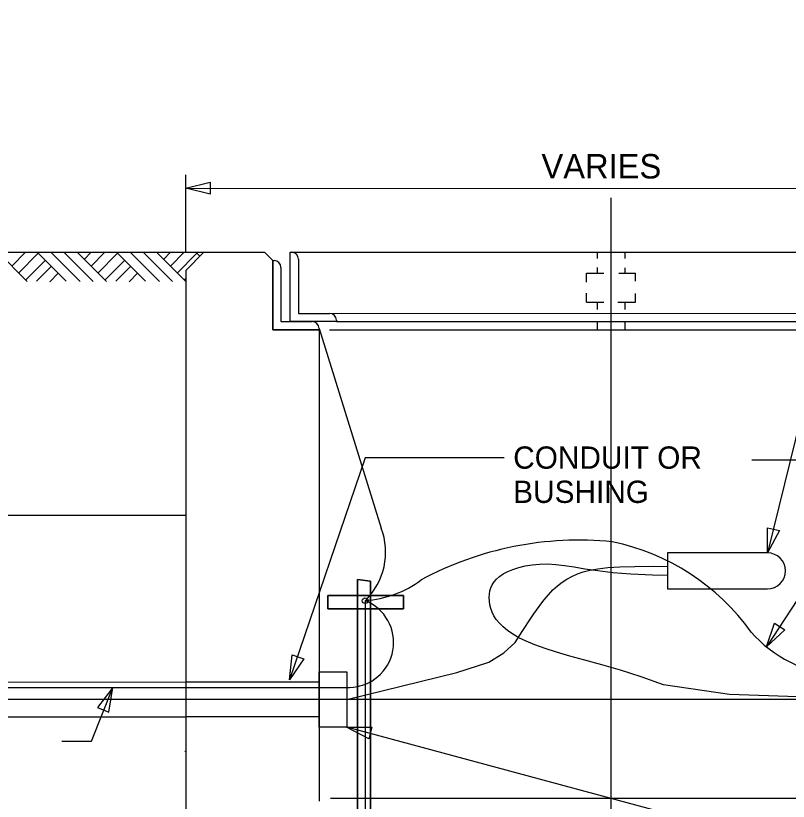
# Model space of a CAD drawing. Extents: x 1299104.8 to 1299141.6, y 239639.8 to 239661.8.
# Drawn here: x 1299124.467 to 1299128.261, y 239648.164 to 239652.024 of the extents above; entities that cross this region are included whole.
import ezdxf

# ---------------------------------------------------------------- set-up
doc = ezdxf.new("R2010")
doc.units = 0
doc.layers.add('DIM TXT', color=7, linetype='Continuous')

msp = doc.modelspace()

# ---------------------------------------------------------------- linework, layer by layer
at = {"layer": 'DIM TXT'}
for p, q in [((1299128.804, 239652.0235), (1299128.1595, 239649.3845)), ((1299125.3013, 239650.8613), (1299125.3013, 239651.2424)), ((1299125.3013, 239651.1756), (1299129.4791, 239651.1753)), ((1299127.3903, 239651.1285), (1299127.3903, 239650.0543)), ((1299123.9914, 239650.8613), (1299125.3906, 239650.8613)), ((1299124.5226, 239650.7182), (1299124.3784, 239650.8613)), ((1299124.5148, 239650.8613), (1299124.4475, 239650.7934)), ((1299124.5764, 239650.8563), (1299124.4803, 239650.7594)), ((1299124.7143, 239650.7194), (1299124.5714, 239650.8613)), ((1299124.7827, 239650.7182), (1299124.6385, 239650.8613)), ((1299124.8475, 239650.7182), (1299124.7033, 239650.8613)), ((1299124.9124, 239650.7182), (1299124.7682, 239650.8613)), ((1299124.8373, 239650.8613), (1299124.803, 239650.8267)), ((1299124.9047, 239650.8613), (1299124.8373, 239650.7934)), ((1299124.9663, 239650.8563), (1299124.8701, 239650.7594)), ((1299125.1041, 239650.7194), (1299124.9613, 239650.8613)), ((1299125.1725, 239650.7182), (1299125.0283, 239650.8613)), ((1299125.2374, 239650.7182), (1299125.0932, 239650.8613)), ((1299125.3023, 239650.7182), (1299125.1581, 239650.8613)), ((1299125.2271, 239650.8613), (1299125.1929, 239650.8267)), ((1299125.2945, 239650.8613), (1299125.2272, 239650.7934)), ((1299125.3561, 239650.8563), (1299125.26, 239650.7594)), ((1299125.3016, 239650.7723), (1299125.3906, 239650.8613)), ((1299125.3709, 239650.8416), (1299125.3511, 239650.8613)), ((1299125.3906, 239650.8613), (1299125.6891, 239650.8613)), ((1299125.6891, 239650.8613), (1299125.7292, 239650.8212)), ((1299125.8151, 239650.8618), (1299125.8212, 239650.8618)), ((1299125.8151, 239650.8618), (1299128.2296, 239650.8618)), ((1299127.3225, 239650.8618), (1299127.3225, 239650.8314)), ((1299127.4581, 239650.8618), (1299127.4581, 239650.83)), ((1299128.2296, 239650.8618), (1299128.9655, 239650.8618)), ((1299124.6114, 239650.8215), (1299124.516, 239650.7254)), ((1299125.0013, 239650.8215), (1299124.9058, 239650.7254)), ((1299125.7292, 239650.8212), (1299125.7353, 239650.8212)), ((1299125.7292, 239650.8212), (1299125.7292, 239650.4807)), ((1299124.6413, 239650.7919), (1299124.5688, 239650.7189)), ((1299125.0311, 239650.7919), (1299124.9586, 239650.7189)), ((1299125.3013, 239650.7719), (1299125.3013, 239648.4563)), ((1299127.3225, 239650.7865), (1299127.3225, 239650.7592)), ((1299127.4581, 239650.7851), (1299127.4581, 239650.7592)), ((1299124.6748, 239650.7586), (1299124.6334, 239650.7169)), ((1299125.0646, 239650.7586), (1299125.0233, 239650.7169)), ((1299125.3013, 239650.731), (1299125.2957, 239650.7254)), ((1299127.2693, 239650.7151), (1299127.2693, 239650.7592)), ((1299127.2693, 239650.7592), (1299127.3547, 239650.7592)), ((1299127.4289, 239650.7592), (1299127.5113, 239650.7592)), ((1299127.5113, 239650.7193), (1299127.5113, 239650.7592)), ((1299127.2693, 239650.6156), (1299127.2693, 239650.6604)), ((1299127.5113, 239650.6156), (1299127.5113, 239650.659)), ((1299127.2693, 239650.6156), (1299127.3547, 239650.6156)), ((1299127.3225, 239650.6156), (1299127.3225, 239650.5809)), ((1299127.4233, 239650.6156), (1299127.5113, 239650.6156)), ((1299127.4581, 239650.6156), (1299127.4581, 239650.5809)), ((1299126.008, 239650.5614), (1299128.7725, 239650.5615)), ((1299126.0421, 239650.5274), (1299126.0421, 239650.5213)), ((1299126.0421, 239650.5213), (1299128.7385, 239650.5213)), ((1299126.1215, 239650.5213), (1299126.5162, 239650.5213)), ((1299126.6845, 239650.5213), (1299126.798, 239650.5213)), ((1299126.7222, 239650.5213), (1299127.0215, 239650.5213)), ((1299127.3225, 239650.5213), (1299127.3225, 239650.4818)), ((1299127.4581, 239650.5213), (1299127.4581, 239650.4818)), ((1299125.7292, 239650.4807), (1299125.9562, 239650.4807)), ((1299125.9562, 239650.4867), (1299125.9562, 239650.4807)), ((1299125.9562, 239650.4867), (1299126.2613, 239649.5068)), ((1299125.9562, 239650.4807), (1299125.9562, 239650.1869)), ((1299126.008, 239650.4807), (1299126.2742, 239650.4807)), ((1299126.2742, 239650.4807), (1299128.4396, 239650.4807)), ((1299125.9562, 239650.1869), (1299125.9562, 239648.1643)), ((1299127.3903, 239650.0543), (1299127.3903, 239646.816)), ((1299124.0638, 239649.5699), (1299125.3013, 239649.5699)), ((1299126.1827, 239649.1498), (1299126.1827, 239646.4459)), ((1299126.9546, 239648.9982), (1299127.0021, 239649.0704)), ((1299126.9199, 239648.9447), (1299126.9546, 239648.9982)), ((1299126.8635, 239648.8937), (1299126.9199, 239648.9447)), ((1299126.791, 239648.8476), (1299126.8635, 239648.8937)), ((1299126.6326, 239648.7976), (1299126.791, 239648.8476)), ((1299126.0924, 239648.6647), (1299126.6326, 239648.7976)), ((1299123.0217, 239648.7524), (1299125.3022, 239648.7501)), ((1299123.0217, 239648.7234), (1299126.1065, 239648.7237)), ((1299125.9562, 239648.7498), (1299125.3013, 239648.7498)), ((1299132.1436, 239648.6647), (1299122.9138, 239648.6647)), ((1299123.0217, 239648.5795), (1299125.3013, 239648.5793)), ((1299125.9564, 239648.5793), (1299125.3013, 239648.5793)), ((1299125.9562, 239648.5285), (1299125.9562, 239648.5285)), ((1299125.3016, 239648.5034), (1299125.3016, 239647.5623)), ((1299125.3003, 239648.4088), (1299125.2972, 239648.4084)), ((1299126.0134, 239648.1789), (1299128.7717, 239648.1789))]:
    msp.add_line(p, q, dxfattribs=at)
for points in [[(1299129.9567, 239651.3812), (1299129.7633, 239651.3812), (1299128.1534, 239648.9236)], [(1299126.0421, 239650.5213), (1299125.8151, 239650.5213), (1299125.8151, 239650.8618)], [(1299125.9562, 239650.4807), (1299125.7292, 239650.4807), (1299125.7292, 239650.8212)], [(1299125.8552, 239650.8278), (1299125.8552, 239650.5614), (1299126.008, 239650.5614)], [(1299125.7693, 239650.7871), (1299125.7693, 239650.5208), (1299125.9222, 239650.5208)], [(1299126.8663, 239649.8521), (1299126.1832, 239649.8523), (1299125.8116, 239648.7617)], [(1299128.0822, 239649.8412), (1299128.3529, 239649.8412), (1299128.6881, 239648.8009)], [(1299128.1595, 239649.3845), (1299127.6671, 239649.3845), (1299127.6671, 239649.2082), (1299128.1595, 239649.2082)], [(1299128.6881, 239648.6647), (1299127.9731, 239648.6881), (1299127.6489, 239648.7358), (1299127.5381, 239648.7761), (1299127.4368, 239648.8086), (1299127.3448, 239648.8352), (1299127.262, 239648.8575), (1299127.1882, 239648.8775), (1299127.1231, 239648.8964), (1299127.0662, 239648.9148), (1299127.0169, 239648.9328), (1299126.9744, 239648.9504), (1299126.9381, 239648.9679), (1299126.9074, 239648.9854), (1299126.8815, 239649.0029), (1299126.8599, 239649.0207), (1299126.8419, 239649.0387), (1299126.8271, 239649.057), (1299126.8154, 239649.0754), (1299126.8065, 239649.0938), (1299126.8, 239649.1121), (1299126.7956, 239649.1301), (1299126.7933, 239649.1478), (1299126.7925, 239649.1651), (1299126.7933, 239649.1818), (1299126.7957, 239649.1979), (1299126.8, 239649.2134), (1299126.8066, 239649.2283), (1299126.8157, 239649.2425), (1299126.8277, 239649.2562), (1299126.8427, 239649.2691), (1299126.8611, 239649.2814), (1299126.8831, 239649.2929), (1299126.9086, 239649.3035), (1299126.9372, 239649.3127), (1299126.9687, 239649.3202), (1299127.0029, 239649.3259), (1299127.0395, 239649.3292), (1299127.0783, 239649.33), (1299127.119, 239649.3279), (1299127.1618, 239649.3228), (1299127.2088, 239649.3154), (1299127.2624, 239649.3066), (1299127.3253, 239649.2973), (1299127.3998, 239649.2885), (1299127.4885, 239649.2811), (1299127.5939, 239649.276), (1299127.6671, 239649.2748)], [(1299127.0021, 239649.0704), (1299127.012, 239649.0852), (1299127.0367, 239649.1206), (1299127.0602, 239649.1516), (1299127.083, 239649.1788), (1299127.1054, 239649.2025), (1299127.1277, 239649.2231), (1299127.1505, 239649.2409), (1299127.174, 239649.2562), (1299127.1987, 239649.2694), (1299127.225, 239649.2809), (1299127.2535, 239649.291), (1299127.2863, 239649.2996), (1299127.3258, 239649.3067), (1299127.3743, 239649.3122), (1299127.4343, 239649.3162), (1299127.5081, 239649.3185), (1299127.5981, 239649.3191), (1299127.6671, 239649.3183)], [(1299126.1445, 239646.4391), (1299126.2093, 239646.4391), (1299126.2093, 239649.2463), (1299126.1445, 239649.2545), (1299126.1445, 239646.4391)], [(1299125.9989, 239649.1102), (1299126.3711, 239649.1102), (1299126.3711, 239649.1749), (1299125.9989, 239649.1749), (1299125.9989, 239649.1102)], [(1299124.6935, 239648.4598), (1299124.8383, 239648.4598), (1299124.9429, 239648.7236)], [(1299126.353, 239648.6647), (1299125.7912, 239648.6647), (1299125.7912, 239648.6647), (1299125.7912, 239648.6647)], [(1299129.7256, 239647.9284), (1299128.3133, 239647.9284), (1299126.0924, 239648.5285)]]:
    msp.add_lwpolyline(points, dxfattribs=at)
for points in [[(1299125.4214, 239651.1462), (1299125.3013, 239651.1756), (1299125.4211, 239651.2062)], [(1299128.2171, 239649.4939), (1299128.1595, 239649.3845), (1299128.1588, 239649.5082)], [(1299126.1445, 239649.2545), (1299126.2093, 239649.2463), (1299126.2093, 239646.4391), (1299126.1445, 239646.4391)], [(1299125.9989, 239649.1749), (1299126.3711, 239649.1749), (1299126.3711, 239649.1102), (1299125.9989, 239649.1102)], [(1299128.244, 239649.0073), (1299128.1534, 239648.9231), (1299128.1937, 239649.04)], [(1299125.8812, 239648.8636), (1299125.8118, 239648.7612), (1299125.8249, 239648.8842)], [(1299125.9562, 239648.5285), (1299125.9562, 239648.8009), (1299126.0924, 239648.8009), (1299126.0924, 239648.5285)], [(1299124.9243, 239648.6013), (1299124.9429, 239648.7236), (1299124.8689, 239648.6245)], [(1299126.2015, 239648.4709), (1299126.092, 239648.5283), (1299126.2156, 239648.5292)]]:
    msp.add_lwpolyline(points, close=True, dxfattribs=at)
msp.add_circle((1299126.1827, 239649.1498), 0.0139, dxfattribs=at)
for centre, radius, start, end in [((1299125.8212, 239650.8278), 0.034, 0, 90), ((1299125.7353, 239650.7871), 0.034, 0, 90), ((1299126.008, 239650.5274), 0.034, 0, 90), ((1299125.9222, 239650.4867), 0.034, 0, 90), ((1299125.9515, 239649.3878), 0.3319, 314.1726, 21.0119), ((1299127.233, 239647.8103), 1.6368, 84.2681, 118.2422), ((1299127.1715, 239648.3462), 1.1156, 35.603, 78.3636), ((1299128.1595, 239649.2963), 0.0881, 270, 90), ((1299126.1463, 239649.6706), 0.522, 273.9922, 306.7263), ((1299126.1019, 239648.9444), 0.2207, 271.1905, 68.5218), ((1299128.5526, 239649.4133), 0.6319, 221.3751, 265.1824)]:
    msp.add_arc(centre, radius, start, end, dxfattribs=at)

# ---------------------------------------------------------------- texts
for s, height, p in [('VARIES', 0.12, (1299127.0488, 239651.224)), ('CONDUIT OR', 0.10943, (1299126.91, 239649.7981)), ('BUSHING', 0.10943, (1299126.91, 239649.63))]:
    msp.add_text(s, height=height, dxfattribs=at).set_placement(p)

doc.saveas('drawing.dxf')
